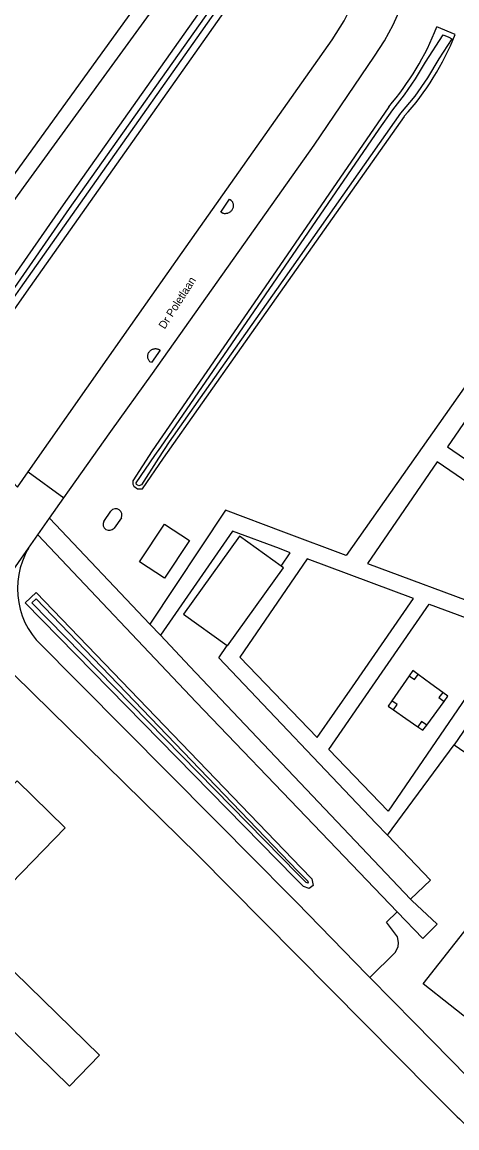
# Model space of a CAD drawing. Extents: x 158132 to 159658, y 385257 to 387209.
# Drawn here: x 159164.8 to 159219.1, y 386145.5 to 386283.7 of the extents above; entities that cross this region are included whole.
import ezdxf

# ---------------------------------------------------------------- set-up
doc = ezdxf.new("R2010")
doc.units = 0
for name, color, linetype in [('IMGEO_Berm_groen', 7, 'Continuous'), ('IMGEO_Grasland_overig', 7, 'Continuous'), ('IMGEO_Groenvoorziening', 7, 'Continuous'), ('IMGEO_Hoogspanningsmast', 7, 'Continuous'), ('IMGEO_Openbare_ruimte_label', 7, 'Continuous'), ('IMGEO_Pand', 7, 'Continuous'), ('IMGEO_Rijbaan_lokaal_gesloten', 7, 'Continuous'), ('IMGEO_Voetpad_onverhard', 7, 'Continuous'), ('IMGEO_Voetpad_open', 7, 'Continuous'), ('IMGEO_Waterloop', 7, 'Continuous')]:
    doc.layers.add(name, color=color, linetype=linetype)

msp = doc.modelspace()

# ---------------------------------------------------------------- linework, layer by layer
at = {"layer": 'IMGEO_Berm_groen'}
msp.add_lwpolyline([(159199.67, 386178.04), (159201, 386176.66), (159201.17, 386175.82), (159200.67, 386175.45), (159199.96, 386175.71), (159198.84, 386176.85), (159165.19, 386211.16), (159166.58, 386212.46), (159199.67, 386178.04)], dxfattribs=at)
at = {"layer": 'IMGEO_Grasland_overig'}
for points in [[(159213.15, 386202.03), (159210.97, 386198.92)], [(159217.33, 386199.96), (159215.85, 386201.04), (159214.26, 386202.22)], [(159215.34, 386195.88), (159217.5, 386198.84)], [(159211.17, 386197.8), (159212.74, 386196.71), (159214.21, 386195.68)]]:
    msp.add_lwpolyline(points, dxfattribs=at)
at = {"layer": 'IMGEO_Groenvoorziening'}
for points in [[(159165.33, 386250), (159161.33, 386244.31), (159159.51, 386243.8), (159159.35, 386244.05), (159158.83, 386244.87), (159162.4, 386250), (159170, 386260.93), (159189.65, 386288.81), (159201.19, 386305.95), (159202.72, 386305.62), (159203.39, 386304.27), (159200.67, 386299.93), (159191.67, 386287.4), (159171.81, 386259.21), (159165.33, 386250)], [(159218.88, 386282.19), (159216.6, 386283.14)], [(159210.61, 386273.16), (159194.7, 386250), (159181.07, 386230.16), (159178.63, 386226.4), (159178.66, 386226.01), (159178.75, 386225.73), (159179.21, 386225.43), (159179.44, 386225.43), (159179.83, 386225.4), (159182.45, 386229.24), (159197.07, 386250), (159212.54, 386271.97)]]:
    msp.add_lwpolyline(points, dxfattribs=at)
for centre, radius, start, end in [((159183.55, 386296.19), 35.53, 319.6023, 338.4499), ((159187.02, 386294.88), 34.29, 318.0894, 338.2848)]:
    msp.add_arc(centre, radius, start, end, dxfattribs=at)
at = {"layer": 'IMGEO_Hoogspanningsmast'}
for points in [[(159214.26, 386202.22), (159213.61, 386202.69), (159213.15, 386202.03)], [(159213.15, 386202.03), (159213.81, 386201.58), (159214.26, 386202.22)], [(159217.33, 386199.96), (159216.86, 386199.32), (159217.5, 386198.84)], [(159217.5, 386198.84), (159217.97, 386199.49), (159217.33, 386199.96)], [(159210.97, 386198.92), (159210.52, 386198.26), (159211.17, 386197.8)], [(159211.17, 386197.8), (159211.63, 386198.46), (159210.97, 386198.92)], [(159215.34, 386195.88), (159214.67, 386196.34), (159214.21, 386195.68)], [(159214.21, 386195.68), (159214.87, 386195.23), (159215.34, 386195.88)]]:
    msp.add_lwpolyline(points, dxfattribs=at)
at = {"layer": 'IMGEO_Pand'}
for points in [[(159185.72, 386218.95), (159182.6, 386214.25), (159179.49, 386216.3), (159182.61, 386221.01), (159185.72, 386218.95)], [(159197.15, 386215.75), (159191.94, 386219.49), (159184.95, 386209.75), (159190.4, 386205.83)], [(159190.4, 386205.83), (159190.44, 386205.8), (159197.44, 386215.55), (159197.15, 386215.75)], [(159163.44, 386176.09), (159170.2, 386183.03), (159164.18, 386188.9), (159157.41, 386181.95), (159163.44, 386176.09)], [(159232.71, 386161.38), (159227.41, 386165.56), (159221.63, 386158.23), (159214.88, 386163.55), (159226.42, 386178.19), (159238.47, 386168.69), (159232.71, 386161.38)], [(159156.54, 386164.61), (159170.75, 386150.77), (159174.49, 386154.61), (159160.28, 386168.45), (159156.54, 386164.61)]]:
    msp.add_lwpolyline(points, dxfattribs=at)
at = {"layer": 'IMGEO_Rijbaan_lokaal_gesloten'}
for points in [[(159170.03, 386224.27), (159170.74, 386225.28), (159175.91, 386232.57), (159181.1, 386239.84), (159201.29, 386268.36), (159208.81, 386279.5), (159210.07, 386281.4), (159211.16, 386283.39), (159212.08, 386285.46), (159212.82, 386287.61), (159213.38, 386289.81), (159213.75, 386292.05), (159213.93, 386294.31), (159213.93, 386296.59), (159213.73, 386298.85), (159213.34, 386301.09), (159212.77, 386303.28), (159212.01, 386305.42), (159211.08, 386307.49), (159210.12, 386309.33)], [(159165.56, 386227.52), (159175.44, 386241.64), (159184.79, 386254.95), (159194.15, 386268.25), (159203.54, 386281.54), (159205.02, 386283.9), (159206.28, 386286.39), (159207.3, 386288.99), (159207.76, 386290.8), (159208.08, 386292.65), (159208.24, 386294.51), (159208.25, 386296.38), (159208.1, 386298.24), (159207.8, 386300.09), (159207.36, 386301.9), (159206.76, 386303.68), (159206.02, 386305.39), (159205.33, 386306.69)], [(159189.82, 386259.86), (159189.62, 386260), (159190.71, 386261.6), (159190.91, 386261.5), (159190.97, 386261.43), (159191.02, 386261.35), (159191.07, 386261.28), (159191.1, 386261.19), (159191.13, 386261.11), (159191.16, 386261.02), (159191.17, 386260.93), (159191.18, 386260.84), (159191.18, 386260.76), (159191.17, 386260.66), (159191.15, 386260.58), (159191.13, 386260.49), (159191.09, 386260.41), (159191.05, 386260.33), (159191.01, 386260.25), (159190.95, 386260.18), (159190.89, 386260.11), (159190.83, 386260.05), (159190.76, 386259.99), (159190.68, 386259.94), (159190.61, 386259.9), (159190.52, 386259.87), (159190.44, 386259.84), (159190.35, 386259.82), (159190.26, 386259.81), (159190.17, 386259.8), (159190.08, 386259.8), (159189.99, 386259.82), (159189.91, 386259.84), (159189.82, 386259.86)], [(159180.77, 386241.3), (159180.71, 386241.36), (159180.66, 386241.43), (159180.62, 386241.51), (159180.58, 386241.58), (159180.55, 386241.66), (159180.53, 386241.75), (159180.51, 386241.83), (159180.5, 386241.91), (159180.5, 386242), (159180.51, 386242.09), (159180.52, 386242.17), (159180.54, 386242.25), (159180.57, 386242.33), (159180.61, 386242.41), (159180.65, 386242.48), (159180.7, 386242.55), (159180.75, 386242.62), (159180.81, 386242.68), (159180.88, 386242.74), (159180.95, 386242.79), (159181.02, 386242.83), (159181.1, 386242.86), (159181.18, 386242.89), (159181.26, 386242.92), (159181.35, 386242.93), (159181.43, 386242.94), (159181.52, 386242.94), (159181.6, 386242.93), (159181.68, 386242.91), (159181.77, 386242.89), (159181.85, 386242.86), (159182.05, 386242.75), (159180.95, 386241.19), (159180.77, 386241.3)], [(159164.23, 386225.62), (159165.56, 386227.52)], [(159165.56, 386227.52), (159170.03, 386224.27)], [(159168.24, 386221.73), (159170.03, 386224.27)], [(159166.79, 386219.66), (159168.24, 386221.73)], [(159165.6, 386217.98), (159166.79, 386219.66)], [(159152.42, 386199.12), (159165.6, 386217.98)], [(159165.6, 386217.98), (159165.49, 386217.77), (159165.19, 386217.2), (159164.85, 386216.39), (159164.59, 386215.56), (159164.39, 386214.7), (159164.28, 386213.83), (159164.24, 386212.96), (159164.27, 386212.08), (159164.39, 386211.21), (159164.58, 386210.36), (159164.84, 386209.52), (159165.17, 386208.71), (159165.58, 386207.94), (159166.05, 386207.2), (159166.55, 386206.55), (159194.19, 386178.66), (159197.66, 386175.17), (159199.08, 386173.74), (159207.91, 386164.65), (159208.23, 386164.33)], [(159215.95, 386150.12), (159194.97, 386171.32), (159186.76, 386179.61), (159163.78, 386202.2)], [(159208.23, 386164.33), (159213.8, 386158.66), (159220.48, 386151.86), (159223.17, 386149.42)]]:
    msp.add_lwpolyline(points, dxfattribs=at)
msp.add_arc((159306.32, 386237.61), 125.79, 224.0718, 227.0544, dxfattribs=at)
at = {"layer": 'IMGEO_Voetpad_onverhard'}
for points in [[(159251.33, 386270), (159245.05, 386274.31), (159226.34, 386247.04), (159205.27, 386217.09), (159197.51, 386219.99), (159190.2, 386222.74), (159180.77, 386208.48)], [(159241.86, 386230.77), (159244.43, 386234.53), (159228.21, 386245.66), (159217.92, 386230.66), (159234.14, 386219.53), (159238.46, 386225.82)], [(159229.96, 386213.47), (159232.86, 386217.68), (159216.63, 386228.79), (159207.94, 386216.09), (159222.98, 386210.48)], [(159197.15, 386215.75), (159198.3, 386217.43), (159196.94, 386217.94), (159191.1, 386220.11), (159182.08, 386207.11)], [(159201.67, 386194.32), (159206.05, 386200.66), (159213.68, 386211.72), (159200.4, 386216.65), (159192.02, 386204.39), (159201.67, 386194.32)], [(159208.56, 386200.73), (159215.64, 386210.99), (159225.68, 386207.27), (159210.51, 386185.11), (159203.11, 386192.82), (159208.56, 386200.73)], [(159226.74, 386187.91), (159237.11, 386203.02), (159227.72, 386206.51), (159218.75, 386193.4)], [(159210.43, 386182.12), (159208.99, 386183.64), (159189.36, 386204.31), (159190.4, 386205.83)]]:
    msp.add_lwpolyline(points, dxfattribs=at)
at = {"layer": 'IMGEO_Voetpad_open'}
for points in [[(159108.85, 386282.06), (159117.57, 386273.34), (159130.65, 386260.4), (159140.34, 386250.7), (159148.1, 386242.94), (159161.05, 386260.86), (159173.19, 386277.68), (159184.91, 386293.93), (159196.39, 386309.76), (159196.57, 386310.04), (159196.71, 386310.34), (159196.84, 386310.64), (159196.93, 386310.96), (159197, 386311.29), (159197.03, 386311.61), (159197.04, 386311.95), (159197.02, 386312.28), (159196.96, 386312.6), (159196.88, 386312.92), (159196.77, 386313.23), (159196.63, 386313.54), (159191.89, 386323.22)], [(159193.9, 386323.08), (159198.04, 386314.97), (159198.39, 386314.26), (159198.59, 386313.85), (159198.75, 386313.41), (159198.86, 386312.97), (159198.94, 386312.51), (159198.98, 386312.05), (159198.98, 386311.58), (159198.94, 386311.12), (159198.86, 386310.66), (159198.73, 386310.21), (159198.57, 386309.77), (159198.37, 386309.35), (159198.14, 386308.95), (159189.78, 386297.34), (159177.03, 386279.71), (159164.93, 386263.08), (159149.39, 386241.45), (159164.23, 386225.62)], [(159180.77, 386208.48), (159168.24, 386221.73)], [(159211.64, 386172.54), (159201.25, 386183.41), (159186.56, 386198.75), (159166.79, 386219.66)], [(159182.08, 386207.11), (159180.77, 386208.48)], [(159213.3, 386174.13), (159185.76, 386203.21), (159182.08, 386207.11)], [(159210.43, 386182.12), (159218.75, 386193.4)], [(159218.75, 386193.4), (159226.74, 386187.91)], [(159213.3, 386174.13), (159215.79, 386176.48), (159210.43, 386182.12)], [(159211.64, 386172.54), (159214.83, 386169.2), (159216.62, 386171.01), (159213.48, 386173.94), (159213.3, 386174.13)], [(159208.23, 386164.33), (159211.4, 386167.46), (159211.62, 386167.84), (159211.76, 386168.21), (159211.81, 386168.66), (159211.78, 386168.98), (159211.7, 386169.41), (159210.3, 386171.26), (159211.64, 386172.54)]]:
    msp.add_lwpolyline(points, dxfattribs=at)
at = {"layer": 'IMGEO_Waterloop'}
for points in [[(159159.89, 386244.8), (159160.8, 386245.06), (159164.63, 386250.49), (159171.11, 386259.7), (159190.97, 386287.9), (159199.95, 386300.41), (159202.4, 386304.32), (159202.13, 386304.87), (159201.58, 386304.99), (159190.36, 386288.32), (159170.71, 386260.44), (159163.1, 386249.51), (159159.86, 386244.85), (159159.89, 386244.8)], [(159183.17, 386231.3), (159181.86, 386229.26), (159179.73, 386225.9), (159179.37, 386225.78), (159179.11, 386225.96), (159179.07, 386226.16), (159181.37, 386229.57), (159182.12, 386230.63), (159195.19, 386249.66), (159209.4, 386270.35), (159211.09, 386272.8), (159212.58, 386274.68), (159213.95, 386276.66), (159215.18, 386278.73), (159217.39, 386282.16), (159218.1, 386281.87), (159218.48, 386281.66), (159216.83, 386279.17), (159215.43, 386276.77), (159213.84, 386274.49), (159212.07, 386272.35), (159196.58, 386250.34), (159183.17, 386231.3)], [(159175.01, 386221.34), (159175.9, 386222.62)], [(159177.21, 386221.79), (159176.3, 386220.51)], [(159200.28, 386176.2), (159199.25, 386177.25), (159166.01, 386211.15), (159166.55, 386211.65), (159199.25, 386177.64), (159200.47, 386176.38), (159200.52, 386176.11), (159200.28, 386176.2)]]:
    msp.add_lwpolyline(points, dxfattribs=at)
for centre, radius, start, end in [((159176.51, 386222.14), 0.78, 333.2602, 141.4291), ((159175.7, 386221), 0.775, 153.612, 320.4121)]:
    msp.add_arc(centre, radius, start, end, dxfattribs=at)

# ---------------------------------------------------------------- texts
at = {"layer": 'IMGEO_Openbare_ruimte_label'}
msp.add_text('Dr Poletlaan', height=1, rotation=57.4541, dxfattribs=at).set_placement((159182.62, 386245.3))

doc.saveas('drawing.dxf')
